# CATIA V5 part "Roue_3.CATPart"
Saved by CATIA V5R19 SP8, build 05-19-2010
Part number: Roue_3
Nomenclature: 70_R3
Bounding box of the stored display mesh (mm): x -6.5 to 6.5, y -6.497 to 6.496, z -1 to 10.4
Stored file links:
  C:\Users\rphgr\Desktop\0_Tapis_TC520B_vitesse\Roue_3.CATPart
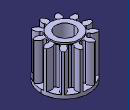
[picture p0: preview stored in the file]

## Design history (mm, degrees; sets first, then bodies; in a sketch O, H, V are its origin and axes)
External parameters (linked from other documents)
  External.Module = 1 mm
  External.Z = 11
  External.DiamPrimitif = 11 mm {= External.Module *External.Z}
  External.AnglePression = 20 deg
  External.x = 0
  External.DeportDenture = 0 mm {= External.x *External.Module}
  External.DiamBase = 10.3366 mm {= External.DiamPrimitif *cos(External.AnglePression )}
  External.DiamPied = 8.5 mm {= External.DiamPrimitif -2.5*External.Module +2*External.DeportDenture}
  External.DiamTete = 13 mm {= External.DiamPrimitif +2*External.Module +2*External.DeportDenture}
  External.PhiPrimitif = 0.854 deg {= atan((sin(External.ThetaPrimitif*1rad)-External.ThetaPrimitif*cos(External.ThetaPrimitif*1rad))/(cos(External.ThetaPrimitif*1rad)+External.ThetaPrimitif*sin(External.ThetaPrimitif*1rad)))}
  External.PhiTete = 6.3669 deg {= atan((sin(External.ThetaTete*1rad)-External.ThetaTete*cos(External.ThetaTete*1rad))/(cos(External.ThetaTete*1rad)+External.ThetaTete*sin(External.ThetaTete*1rad)))}
  External.PhiSymetrie = 8.1818 deg {= 180*1 deg/(2*External.Z )}
  External.CongePied = 0.38 mm {= 0.38*External.Module}
  External.AlphaCopie = 32.7273 deg {= 360*1 deg/External.Z}
  External.AlphaSymetrieCopie = 16.3636 deg {= External.AlphaCopie /2}
  External.CoeffQualiteEngrenage = 7
  External.LargeurDenture = 10 mm
  External.ThetaPrimitif = 0.36397 {= sqrt(abs((External.DiamPrimitif*External.DiamPrimitif)/(External.DiamBase *External.DiamBase )-1))}
  External.ThetaTete = 0.762706 {= sqrt(abs((External.DiamTete*External.DiamTete)/(External.DiamBase *External.DiamBase )-1) )}
  External.Di = 10.6683 mm {= (External.DiamBase +External.DiamPrimitif )/2}
  External.Thetai = 0.255358 {= sqrt(abs((External.Di*External.Di)/(External.DiamBase*External.DiamBase)-1))}
  External.Phii = 0.3061 deg {= atan((sin(External.Thetai*1rad)-External.Thetai*cos(External.Thetai*1rad))/(cos(External.Thetai*1rad)+External.Thetai*sin(External.Thetai*1rad)))}
  External.Dj = 12 mm {= (External.DiamTete+External.DiamPrimitif)/2}
  External.Thetaj = 0.589693 {= sqrt(abs((External.Dj*External.Dj)/(External.DiamBase*External.DiamBase)-1))}
  External.Phij = 3.2594 deg {= atan((sin(External.Thetaj*1rad)-External.Thetaj*cos(External.Thetaj*1rad))/(cos(External.Thetaj*1rad)+External.Thetaj*sin(External.Thetaj*1rad)))}
  External.Dk = 10.5025 mm {= (External.Di+External.DiamBase)/2}
  External.Thetak = 0.179851 {= sqrt(abs((External.Dk*External.Dk)/(External.DiamBase*External.DiamBase)-1))}
  External.Phik = 0.109 deg {= atan((sin(External.Thetak*1rad)-External.Thetak*cos(External.Thetak*1rad))/(cos(External.Thetak*1rad)+External.Thetak*sin(External.Thetak*1rad)))}
  External.Dl = 10.8342 mm {= (External.DiamPrimitif+External.Di)/2}
  External.Thetal = 0.31398 {= sqrt(abs((External.Dl*External.Dl)/(External.DiamBase*External.DiamBase)-1))}
  External.Phil = 0.5585 deg {= atan((sin(External.Thetal*1rad)-External.Thetal*cos(External.Thetal*1rad))/(cos(External.Thetal*1rad)+External.Thetal*sin(External.Thetal*1rad)))}
  External.Dm = 11.5 mm {= (External.Dj+External.DiamPrimitif)/2}
  External.Thetam = 0.487613 {= sqrt(abs((External.Dm*External.Dm)/(External.DiamBase*External.DiamBase)-1))}
  External.Phim = 1.9437 deg {= atan((sin(External.Thetam*1rad)-External.Thetam*cos(External.Thetam*1rad))/(cos(External.Thetam*1rad)+External.Thetam*sin(External.Thetam*1rad)))}
  External.Dn = 12.5 mm {= (External.DiamTete+External.Dj)/2}
  External.Thetan = 0.679992 {= sqrt(abs((External.Dn*External.Dn)/(External.DiamBase*External.DiamBase)-1))}
  External.Phin = 4.7453 deg {= atan((sin(External.Thetan*1rad)-External.Thetan*cos(External.Thetan*1rad))/(cos(External.Thetan*1rad)+External.Thetan*sin(External.Thetan*1rad)))}
  External.DiametreAlesage = 5 mm
Body1 (main body)
  Sketch1 on xy-plane, origin (0, 0, 0), H (1, 0, 0), V (0, 1, 0)
    construction circle A1 centre (0, 0) radius 5.5
    construction circle A2 centre (0, 0) radius 5.1683
    construction circle A3 centre (0, 0) radius 4.25
    construction circle A4 centre (0, 0) radius 6.5
    point P1 (5.1683, 0)
    construction line L1 (5.1683, 0) -> (0, 0)
    point P2 (5.4994, 0.082)
    construction line L2 (5.4994, 0.082) -> (0, 0)
    point P3 (6.4599, 0.7208)
    construction line L3 (6.4599, 0.7208) -> (0, 0)
    construction line L4 (5.1683, 0) -> (5.1683, 3.9367)
    point P4 (5.1683, 0)
    point P6 (4.8372, 0.082)
    construction line L5 (6.4599, 0.7208) -> (5.4994, 0.082)
    point P7 (5.9796, 0.4014)
    point P8 (4.357, 0.4014)
    spline S1 through (4.357, 0.4014) (4.8372, 0.082) (5.1683, 0) (5.2512, 0.01) (5.3341, 0.0285) (5.4168, 0.0528) (5.4994, 0.082) (5.7467, 0.195) (5.9903, 0.3411) (6.2286, 0.517) (6.4599, 0.7208)
    construction line L6 (0, 0) -> (5.2089, 0.8284)
    spline S2 through (4.2666, 0.97) (4.624, 1.4226) (4.9134, 1.6032) (4.9953, 1.6195) (5.0798, 1.6276) (5.166, 1.6301) (5.2535, 1.628) (5.5237, 1.5972) (5.8006, 1.5339) (6.0817, 1.4406) (6.3648, 1.3186)
    arc A5 centre (4.624, -0.235) radius 0.38 from (4.8065, 0.0983) to (4.2445, -0.2157) ccw
    point P11 (4.2445, -0.2157)
    arc A6 centre (0, 0) radius 6.5 from (6.4599, 0.7208) to (6.3648, 1.3186) ccw
    point P13 (6.3648, 1.3186)
    arc A7 centre (4.323, 1.6578) radius 0.38 from (3.9682, 1.5218) to (4.5999, 1.3975) ccw
    point P15 (3.9682, 1.5218)
    construction line L7 (0, 0) -> (3.8692, 1.8372)
    construction line L8 (0, 0) -> (5.084, -0.6538)
    point P19 (3.8392, 1.8229)
    arc A8 centre (0, 0) radius 4.25 from (3.9682, 1.5218) to (3.8392, 1.8229) ccw
    point P20 (4.2153, -0.5421)
    arc A9 centre (0, 0) radius 4.25 from (4.2153, -0.5421) to (4.2445, -0.2157) ccw
    line L9 (3.8392, 1.8229) -> (0, 0)
    line L10 (4.2153, -0.5421) -> (0, 0)
    construction circle A10 centre (0, 0) radius 5.3342
    construction line L11 (0, 0) -> (2.5698, 0.0137)
    point P22 (5.3341, 0.0285)
    construction circle A11 centre (0, 0) radius 6
    construction line L12 (0, 0) -> (4.0126, 0.2285)
    point P24 (5.9903, 0.3411)
    point P25 (5.9903, 0.3411)
    point P26 (5.8006, 1.5339)
    point P27 (5.0798, 1.6276)
    construction circle A12 centre (0, 0) radius 5.2512
    construction line L13 (0, 0) -> (48.2618, 0.0918)
    point P29 (4.9953, 1.6195)
    construction line L14 (0, 0) -> (63.1845, 10.0479)
    point P31 (5.2512, 0.01)
    construction circle A13 centre (0, 0) radius 5.4171
    construction line L15 (0, 0) -> (57.3607, 0.5591)
    point P33 (5.4168, 0.0528)
    point P34 (5.166, 1.6301)
    construction circle A14 centre (0, 0) radius 5.75
    construction line L16 (0, 0) -> (65.6729, 2.2287)
    point P36 (5.7467, 0.195)
    point P37 (5.5237, 1.5972)
    construction circle A15 centre (0, 0) radius 6.25
    axis line L17 (0, 0) -> (59.1475, 4.9099)
    point P39 (6.0817, 1.4406)
    point P40 (6.2286, 0.517)
    point P42 (4.357, 0.4014)
    point P43 (4.8372, 0.082)
    point P44 (5.1683, 0)
    point P45 (5.4994, 0.082)
    point P46 (6.4599, 0.7208)
    point P47 (6.3648, 1.3186)
    point P48 (4.2666, 0.97)
    point P49 (5.2535, 1.628)
    point P50 (4.9134, 1.6032)
    point P51 (4.624, 1.4226)
    point P52 (5.3341, 0.0285)
    point P53 (5.9903, 0.3411)
    point P54 (5.0798, 1.6276)
    point P55 (5.8006, 1.5339)
    point P56 (5.2512, 0.01)
    point P57 (4.9953, 1.6195)
    point P58 (5.4168, 0.0528)
    point P59 (5.166, 1.6301)
    point P60 (5.7467, 0.195)
    point P61 (5.5237, 1.5972)
    point P62 (6.2286, 0.517)
    point P63 (6.0817, 1.4406)
    radius A1 = 5.5 {= External.DiamPrimitif /2}
    radius A2 = 5.1683 {= External.DiamBase /2}
    radius A3 = 4.25 {= External.DiamPied /2}
    radius A4 = 6.5 {= External.DiamTete /2}
    angle L2 L1 = 0.854 {= External.PhiPrimitif}
    angle L3 L1 = 6.3669 {= External.PhiTete}
    angle L4 L1 = 90
    radius A5 = 0.38 {= External.CongePied}
    radius A7 = 0.38 {= External.CongePied}
    angle L7 L6 = 16.3636 {= External.AlphaSymetrieCopie}
    angle L2 L6 = 8.1818 {= External.PhiSymetrie}
    radius A10 = 5.3342 {= External.Di /2}
    angle L11 L1 = 0.3061 {= External.Phii}
    radius A11 = 6 {= External.Dj /2}
    angle L12 L1 = 3.2594 {= External.Phij}
    radius A12 = 5.2512 {= External.Dk/2}
    angle L13 L1 = 0.109 {= External.Phik}
    angle L14 L2 = 8.1818 {= External.PhiSymetrie}
    radius A13 = 5.4171 {= External.Dl /2}
    angle L15 L1 = 0.5585 {= External.Phil}
    radius A14 = 5.75 {= External.Dm /2}
    angle L16 L1 = 1.9437 {= External.Phim}
    radius A15 = 6.25 {= External.Dn/2}
    angle L17 L1 = 4.7453 {= External.Phin}
    coincidence: P1 A2, P1 H, P2 A1, P3 A4, P4 A2, P7 L5, P42 P8, P43 P6, P44 P1, P45 L5, P45 L2, P46 L5, P46 L3, P11 A3, P47 P13, P15 A3, P19 L7, P19 A3, P20 L8, P20 A3, P3 P46, P22 L11, P22 A10, P52 P22, P24 L12, P24 A11, P53 P24, P25 P53, P54 P27, P55 P26, P31 L13, P31 A12, P56 P31, P57 P29, P33 L15, P33 A13, P58 P33, P59 P34, P36 L16, P36 A14, P60 P36, P61 P37, P40 L17, P40 A15, P62 P40, P63 P39, O L9, O L10
    horizontal: L1 H
    tangency: L4 A2, A5 A3, A5 S1, A7 A3, A7 S2, A8 A5, A9 A5
    symmetry: P6 P2 L4, P8 P7 L4, P46 P47 L6, P42 P48 L6, P45 P49 L6, P44 P50 L6, P43 P51 L6, L8 L7 L6, P26 P25 L6, P27 P22 L6, P29 P31 L14, P34 P33 L14, P37 P36 L14, P39 P40 L14
    midpoint: P7 L5
    parallelism: L9 L7, L10 L8
    concentricity: A10 A2, A11 A1
  Pad1: profile Sketch1, direction (0, 0, 1), length 10 {= External.LargeurDenture}
  CircPattern1 "Roue Dentée": of Pad1, instances 11 {= External.Z}, angular step 32.7273 {= External.AlphaCopie}, axis from Z axis
  Body2
    Sketch2 on xy-plane, origin (0, 0, 0), H (1, 0, 0), V (0, 1, 0)
      circle A1 centre (0, 0) radius 2.5
      radius A1 = 2.5 {= External.DiametreAlesage /2}
    Pad2: profile Sketch2, direction (0, 0, 1), length 20 {= 2*External.LargeurDenture}
  Remove1: tool Body2
  Sketch3 on face of CircPattern1, origin (0, 0, 0), H (1, 0, 0), V (0, -1, 0)
    circle A1 centre (0, 0) radius 6.5
    circle A2 centre (0, 0) radius 2.5
    reference projected circle E1 centre (0, 0) radius 2.5 from edge [face of Pad2 from Sketch2.A1 | face of CircPattern1]
    reference projected arc E2 centre (0, 0) radius 6.5 from (6.3648, -1.3186) to (6.4599, -0.7208) ccw from edge [face of CircPattern1 | face of Pad1 from Sketch1.A6]
    coincidence: A2 E1, A1 E2
  Pad3: profile Sketch3, direction (0, 0, -1), length 1
  Sketch4 on face of CircPattern1, origin (0, 0, 10), H (1, 0, 0), V (0, 1, 0)
    circle A1 centre (0, 0) radius 2.5
    circle A2 centre (0, 0) radius 4
    reference projected circle E1 centre (0, 0) radius 2.5 from edge [face of CircPattern1 | face of Pad3]
    distance A2 A1 = 1.5
    coincidence: A1 E1
  Pad4: profile Sketch4, direction (0, 0, 1), length 0.4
